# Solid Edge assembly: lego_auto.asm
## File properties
Author: Romil
Template: Iso Assembly.asm
Last saved by: Romil
Revision: 83
Application: Solid Edge
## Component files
kaarega_must_x_o_o_ojne.par
12_riba_roheline.par
must_3_xox.par
2_pulk_x_o.par
6_pulk.par
3_pulk.par
x.x.risti_must.par
must_konnektor_rist_rist.par
2_pulk.par
x.o.risti_must.par
2_pulk_o_o.par
x.o.risti_hall.par
8_pulk.par
tiib_teine_pool.par
x.x.risti_roheline.par
tiib.par
toru.par
alumine_toru.par
rool.par
peatugi.par
tool.par
4_pulk.par
rattahoidja.par
1.2x_hall_uus.par
ratas.asm
lamp.par
alus.psm
5_pulk.par
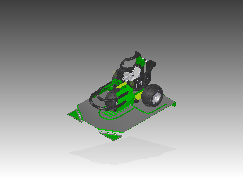
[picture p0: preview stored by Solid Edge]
